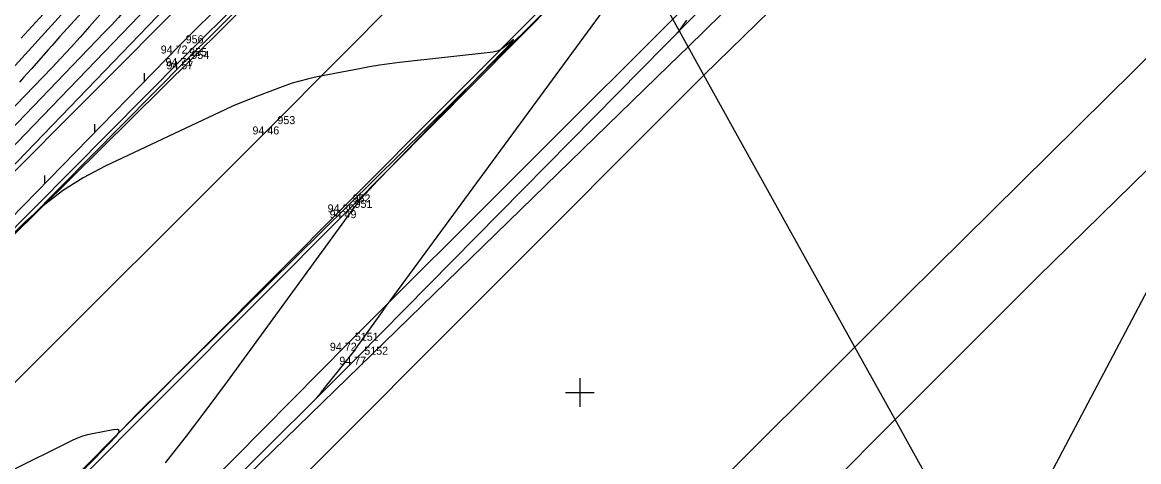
# Model space of a CAD drawing. Extents: x -711081 to -709338, y -1025122 to -1024092.
# Drawn here: x -709594.51 to -709555.44, y -1024302.42 to -1024287.05 of the extents above; entities that cross this region are included whole.
import ezdxf

# ---------------------------------------------------------------- set-up
doc = ezdxf.new("R2010")
doc.units = 0
for name, color, linetype in [('Ex_Major Contours', 7, 'Continuous'), ('Ex_Minor Contours', 7, 'Continuous'), ('Z_body', 7, 'Continuous'), ('Z_body_cisla', 7, 'Continuous'), ('Z_body_vysky_redukovane', 7, 'Continuous'), ('Z_hektometricka_sit', 7, 'Continuous'), ('Z_hrany_paty', 7, 'Continuous'), ('Z_katastr_hranice', 7, 'Continuous'), ('Z_katastr_vnitrni_kresba', 7, 'Continuous'), ('Z_komunikace', 7, 'Continuous'), ('Z_obruba', 7, 'Continuous'), ('Z_rozhranni', 7, 'Continuous'), ('Z_svodidla', 7, 'Continuous'), ('Z_svodidla_znacky', 7, 'Continuous'), ('Z_vdz12_prerusovana', 7, 'Continuous')]:
    doc.layers.add(name, color=color, linetype=linetype)

# ---------------------------------------------------------------- blocks, each defined once
blk = doc.blocks.new('POINT_DISPLAY')
blk.add_line((0, 0), (0, 0))
blk = doc.blocks.new('Z529')
blk.add_line((0, 0), (0.2, 0.2))

msp = doc.modelspace()

# ---------------------------------------------------------------- linework, layer by layer
at = {"layer": 'Ex_Major Contours'}
for points in [[(-709579.489, -1024274.455), (-709586.452, -1024281.668), (-709586.737, -1024281.965), (-709587.02, -1024282.266), (-709587.3, -1024282.568), (-709587.577, -1024282.874), (-709588.749, -1024284.175), (-709588.99, -1024284.444), (-709589.231, -1024284.714), (-709589.47, -1024284.984), (-709589.709, -1024285.255), (-709590.663, -1024286.34), (-709590.903, -1024286.61), (-709591.146, -1024286.877), (-709591.392, -1024287.142), (-709591.641, -1024287.403), (-709596.883, -1024292.846)], [(-709592.88, -1024285.765), (-709594.547, -1024287.602)], [(-709571.267, -1024286.968), (-709571.582, -1024287.411)]]:
    msp.add_lwpolyline(points, dxfattribs=at)
at = {"layer": 'Ex_Minor Contours'}
for points in [[(-709584.22, -1024300.204), (-709584.053, -1024300.001), (-709584.025, -1024299.967), (-709583.998, -1024299.933), (-709583.97, -1024299.899), (-709583.943, -1024299.865), (-709583.168, -1024298.899), (-709583.031, -1024298.725), (-709582.897, -1024298.55), (-709582.765, -1024298.373), (-709582.636, -1024298.194), (-709581.847, -1024297.083), (-709581.829, -1024297.059), (-709581.812, -1024297.034), (-709581.794, -1024297.01), (-709581.776, -1024296.986), (-709581.705, -1024296.89), (-709581.669, -1024296.841), (-709581.634, -1024296.793), (-709572.497, -1024284.353)], [(-709598.667, -1024296.044), (-709587.962, -1024284.93)], [(-709591.993, -1024285.506), (-709595.337, -1024289.191)], [(-709591.106, -1024285.248), (-709593.052, -1024287.392), (-709593.194, -1024287.549), (-709593.336, -1024287.708), (-709593.478, -1024287.867), (-709593.618, -1024288.026), (-709594.18, -1024288.666), (-709594.321, -1024288.825), (-709594.464, -1024288.982), (-709594.609, -1024289.138)], [(-709590.859, -1024285.724), (-709592.153, -1024287.198), (-709592.479, -1024287.564), (-709592.808, -1024287.927), (-709593.142, -1024288.285), (-709593.48, -1024288.64), (-709595.992, -1024291.247)], [(-709597.775, -1024294.445), (-709589.801, -1024286.166)], [(-709589.499, -1024302.467), (-709588.763, -1024301.526), (-709588.04, -1024300.575), (-709587.329, -1024299.614), (-709583.215, -1024293.98), (-709583.157, -1024293.901), (-709583.099, -1024293.822), (-709583.042, -1024293.743), (-709582.984, -1024293.664), (-709582.752, -1024293.349), (-709582.693, -1024293.271), (-709582.631, -1024293.196), (-709582.568, -1024293.122), (-709582.502, -1024293.049), (-709582.079, -1024292.6), (-709581.986, -1024292.501), (-709581.893, -1024292.403), (-709581.799, -1024292.305), (-709581.705, -1024292.208), (-709577.365, -1024287.729), (-709577.315, -1024287.676), (-709577.302, -1024287.655), (-709577.324, -1024287.666), (-709577.383, -1024287.71), (-709577.688, -1024287.949), (-709577.767, -1024288.003), (-709577.851, -1024288.044), (-709577.939, -1024288.073), (-709578.033, -1024288.09), (-709581.303, -1024288.457), (-709581.656, -1024288.5), (-709582.007, -1024288.55), (-709582.358, -1024288.607), (-709582.707, -1024288.672), (-709584.251, -1024288.972), (-709584.524, -1024289.031), (-709584.794, -1024289.101), (-709585.06, -1024289.182), (-709585.324, -1024289.274), (-709586.371, -1024289.665), (-709586.632, -1024289.766), (-709586.89, -1024289.872), (-709587.146, -1024289.983), (-709587.4, -1024290.099), (-709591.611, -1024292.083), (-709592.376, -1024292.484), (-709593.099, -1024292.944), (-709593.781, -1024293.464), (-709594.42, -1024294.045), (-709597.895, -1024297.473)], [(-709592.198, -1024302.548), (-709592.06, -1024302.404), (-709591.923, -1024302.259), (-709591.785, -1024302.115), (-709591.215, -1024301.513), (-709591.126, -1024301.4), (-709591.115, -1024301.329), (-709591.181, -1024301.3), (-709591.324, -1024301.312), (-709592.049, -1024301.443), (-709592.228, -1024301.482), (-709592.403, -1024301.533), (-709592.574, -1024301.597), (-709592.741, -1024301.673), (-709595.035, -1024302.813)]]:
    msp.add_lwpolyline(points, dxfattribs=at)
at = {"layer": 'Z_hektometricka_sit'}
for p, q in [((-709575, -1024299.5), (-709575, -1024300.5)), ((-709575.5, -1024300), (-709574.5, -1024300))]:
    msp.add_line(p, q, dxfattribs=at)
at = {"layer": 'Z_hrany_paty'}
msp.add_line((-709586.49, -1024283.94), (-709598.81, -1024296.3), dxfattribs=at)
at = {"layer": 'Z_katastr_hranice'}
for p, q in [((-709551.32, -1024268.36), (-709571.21, -1024287.91)), ((-709571.21, -1024287.91), (-709573.42, -1024283.89)), ((-709571.21, -1024287.91), (-709571.87, -1024288.55)), ((-709570.66, -1024288.9), (-709571.21, -1024287.91)), ((-709560.66, -1024306.9), (-709550.52, -1024287.67)), ((-709571.87, -1024288.55), (-709587.68, -1024303.92)), ((-709565.37, -1024298.41), (-709570.66, -1024288.9)), ((-709563.96, -1024300.95), (-709565.37, -1024298.41)), ((-709560.66, -1024306.9), (-709563.96, -1024300.95))]:
    msp.add_line(p, q, dxfattribs=at)
at = {"layer": 'Z_katastr_vnitrni_kresba'}
for p, q in [((-709570.66, -1024288.9), (-709536.6, -1024255.45)), ((-709577.18, -1024277.05), (-709594.94, -1024294.62)), ((-709563.57, -1024296.61), (-709545.91, -1024279.14)), ((-709590.48, -1024300.74), (-709573.42, -1024283.89)), ((-709558.99, -1024295.98), (-709550.52, -1024287.67)), ((-709571.1, -1024289.34), (-709570.66, -1024288.9)), ((-709585.38, -1024303.64), (-709571.1, -1024289.34)), ((-709563.96, -1024300.95), (-709558.99, -1024295.98)), ((-709565.37, -1024298.41), (-709563.57, -1024296.61)), ((-709577.71, -1024310.7), (-709565.37, -1024298.41)), ((-709640.14, -1024352.3), (-709590.48, -1024300.74)), ((-709575.83, -1024312.82), (-709563.96, -1024300.95))]:
    msp.add_line(p, q, dxfattribs=at)
at = {"layer": 'Z_komunikace'}
for p, q in [((-709588.81, -1024288.41), (-709577.3, -1024276.99)), ((-709583.17, -1024293.42), (-709573.48, -1024283.69)), ((-709582.76, -1024298.75), (-709568.18, -1024283.96)), ((-709599.43, -1024299.13), (-709588.81, -1024288.41)), ((-709594.3, -1024304.6), (-709583.17, -1024293.42)), ((-709597.36, -1024313.29), (-709582.76, -1024298.75))]:
    msp.add_line(p, q, dxfattribs=at)
at = {"layer": 'Z_obruba'}
for p, q in [((-709588.89, -1024288.3), (-709577.41, -1024276.88)), ((-709583.1, -1024293.62), (-709573.45, -1024283.88)), ((-709599.48, -1024298.98), (-709588.89, -1024288.3)), ((-709594.13, -1024304.68), (-709583.1, -1024293.62))]:
    msp.add_line(p, q, dxfattribs=at)
at = {"layer": 'Z_rozhranni'}
for p, q in [((-709583.09, -1024298.26), (-709568.41, -1024283.6)), ((-709597.61, -1024312.95), (-709583.09, -1024298.26))]:
    msp.add_line(p, q, dxfattribs=at)
at = {"layer": 'Z_svodidla'}
for p, q in [((-709589.01, -1024287.86), (-709577.8, -1024276.67)), ((-709599.83, -1024298.95), (-709589.01, -1024287.86))]:
    msp.add_line(p, q, dxfattribs=at)
at = {"layer": 'Z_vdz12_prerusovana'}
for p, q in [((-709585.8, -1024290.69), (-709574.66, -1024279.5)), ((-709597.25, -1024302.12), (-709585.8, -1024290.69))]:
    msp.add_line(p, q, dxfattribs=at)

# ---------------------------------------------------------------- block references
at = {"layer": 'Z_body'}
for p in [(-709589.01, -1024287.86), (-709588.89, -1024288.3), (-709588.81, -1024288.41), (-709585.8, -1024290.69), (-709583.17, -1024293.42), (-709583.1, -1024293.62), (-709583.09, -1024298.26), (-709582.76, -1024298.75)]:
    msp.add_blockref('POINT_DISPLAY', p, dxfattribs=at)
at = {"layer": 'Z_svodidla_znacky', "rotation": 45.7}
for p in [(-709590.23, -1024289.11), (-709591.97, -1024290.9), (-709593.72, -1024292.69)]:
    msp.add_blockref('Z529', p, dxfattribs=at)

# ---------------------------------------------------------------- texts
at = {"layer": 'Z_body_cisla'}
for s, p in [('956', (-709588.79, -1024287.78)), ('955', (-709588.67, -1024288.23)), ('954', (-709588.59, -1024288.33)), ('953', (-709585.58, -1024290.61)), ('952', (-709582.95, -1024293.35)), ('951', (-709582.88, -1024293.54)), ('5151', (-709582.87, -1024298.19)), ('5152', (-709582.54, -1024298.68))]:
    msp.add_text(s, height=0.28, dxfattribs=at).set_placement(p)
at = {"layer": 'Z_body_vysky_redukovane'}
for s, p in [('94 72', (-709589.663, -1024288.14)), ('94 71', (-709589.497, -1024288.58)), ('94 57', (-709589.463, -1024288.69)), ('94 46', (-709586.453, -1024290.97)), ('94 39', (-709583.823, -1024293.7)), ('94 49', (-709583.753, -1024293.9)), ('94 72', (-709583.743, -1024298.54)), ('94 77', (-709583.413, -1024299.03))]:
    msp.add_text(s, height=0.28, dxfattribs=at).set_placement(p)

doc.saveas('drawing.dxf')
